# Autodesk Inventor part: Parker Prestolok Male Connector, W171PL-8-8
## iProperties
Shininess: 20.0
Length Units: 11272
Angle Units: 11279
Time Units: 11290
Mass Units: 11286
Length Display Precision: 3
Angle Display Precision: 2
Created: 2001-09
Part Number: Parker Prestolok Male Connector, W171PL-8-8
Material: Stainless Steel, Austenitic
Description: Parker Prestolok Male Connector, W171PL-8-8
Document SubType Name: Modeling
Designer: jhagarty
Density: 0.0
Volumn: 0.0
Area: 0.0
PropertySet Name: Model Information
Control State: 0
Master: False
Checked Out: False
Author: jhagarty
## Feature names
1. Extrusion1
2. Revolution3
3. Mirror2
4. Extrusion2
5. Extrusion4
6. Extrusion5
7. Extrusion6
8. Revolution6
9. Extrusion7
10. Extrusion8
11. Revolution7
12. Revolution8
13. Extrusion9
14. Extrusion10
15. Revolution11
16. Revolution12
17. Hole4
18. Hole5
19. Hole6
